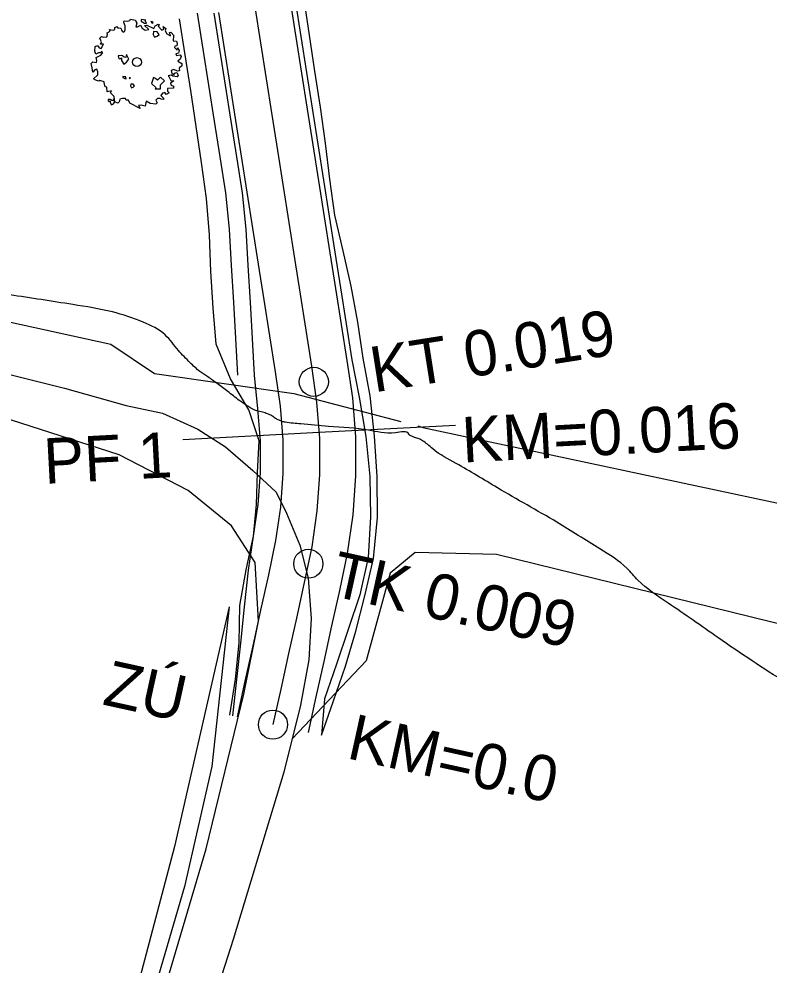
# Model space of a CAD drawing. Extents: x -477701 to -476785, y -1116511 to -1115314.
# Drawn here: x -477305.1 to -477263.9, y -1116246.2 to -1116194.2 of the extents above; entities that cross this region are included whole.
import ezdxf

# ---------------------------------------------------------------- set-up
doc = ezdxf.new("R2010")
doc.units = 0
for name, color, linetype in [('1', 7, 'Continuous'), ('BYBLOCK', 7, 'Continuous'), ('hrana_P', 7, 'Continuous'), ('hrana_R', 7, 'Continuous'), ('IP_RBK', 7, 'Continuous'), ('POLYGONY_SITUACE_PF', 7, 'Continuous'), ('POLYGONY_SITUACE_PF_POPISY', 7, 'Continuous'), ('POLYGONY_SITUACE_PO', 7, 'Continuous'), ('SVK_STAT', 7, 'Continuous'), ('Vrstevnice_vedlejsi', 7, 'Continuous')]:
    doc.layers.add(name, color=color, linetype=linetype)

msp = doc.modelspace()

# ---------------------------------------------------------------- linework, layer by layer
at = {"layer": 'hrana_P'}
for points in [[(-477289.157, -1116195.055), (-477289.457, -1116193.078)], [(-477295.992, -1116196.133), (-477296.298, -1116194.157)], [(-477288.856, -1116197.033), (-477289.157, -1116195.055)], [(-477295.686, -1116198.109), (-477295.992, -1116196.133)], [(-477288.556, -1116199.01), (-477288.856, -1116197.033)], [(-477295.381, -1116200.086), (-477295.686, -1116198.109)], [(-477288.281, -1116200.991), (-477288.556, -1116199.01)], [(-477295.098, -1116202.066), (-477295.381, -1116200.086)], [(-477288.031, -1116202.977), (-477288.281, -1116200.991)], [(-477294.816, -1116204.046), (-477295.098, -1116202.066)], [(-477287.755, -1116204.958), (-477288.031, -1116202.977)], [(-477294.65, -1116206.045), (-477294.816, -1116204.046)], [(-477287.314, -1116206.913), (-477287.755, -1116204.958)], [(-477294.576, -1116208.058), (-477294.65, -1116206.045)], [(-477286.873, -1116208.868), (-477287.314, -1116206.913)], [(-477294.444, -1116210.062), (-477294.576, -1116208.058)], [(-477286.508, -1116210.835), (-477286.873, -1116208.868)], [(-477294.284, -1116212.061), (-477294.444, -1116210.062)], [(-477286.213, -1116212.814), (-477286.508, -1116210.835)], [(-477293.502, -1116213.963), (-477294.284, -1116212.061)], [(-477285.823, -1116214.902), (-477286.213, -1116212.814)], [(-477292.484, -1116215.668), (-477293.502, -1116213.963)], [(-477285.587, -1116217.111), (-477285.823, -1116214.902)], [(-477291.919, -1116217.368), (-477292.484, -1116215.668)], [(-477292.011, -1116219.119), (-477291.919, -1116217.368)], [(-477285.428, -1116219.34), (-477285.587, -1116217.111)], [(-477292.073, -1116220.868), (-477292.011, -1116219.119)], [(-477285.425, -1116221.587), (-477285.428, -1116219.34)], [(-477292.236, -1116222.618), (-477292.073, -1116220.868)], [(-477285.632, -1116223.832), (-477285.425, -1116221.587)], [(-477292.629, -1116224.463), (-477292.236, -1116222.618)], [(-477286.111, -1116225.897), (-477285.632, -1116223.832)], [(-477292.984, -1116226.433), (-477292.629, -1116224.463)], [(-477286.601, -1116227.837), (-477286.111, -1116225.897)], [(-477293.014, -1116228.474), (-477292.984, -1116226.433)], [(-477287.183, -1116229.757), (-477286.601, -1116227.837)], [(-477293.222, -1116230.476), (-477293.014, -1116228.474)], [(-477287.84, -1116231.66), (-477287.183, -1116229.757)], [(-477293.532, -1116232.455), (-477293.222, -1116230.476)], [(-477288.503, -1116233.562), (-477287.84, -1116231.66)]]:
    msp.add_lwpolyline(points, dxfattribs=at)
at = {"layer": 'hrana_R'}
for points in [[(-477289.881, -1116195.169), (-477290.192, -1116193.194)], [(-477289.945, -1116193.155), (-477289.634, -1116195.131)], [(-477294.998, -1116195.831), (-477295.309, -1116193.856)], [(-477294.079, -1116195.831), (-477294.39, -1116193.856)], [(-477293.832, -1116195.792), (-477294.143, -1116193.817)], [(-477292.168, -1116193.505), (-477291.856, -1116195.481)], [(-477291.856, -1116195.481), (-477291.545, -1116197.457)], [(-477289.569, -1116197.145), (-477289.881, -1116195.169)], [(-477289.634, -1116195.131), (-477289.322, -1116197.106)], [(-477294.686, -1116197.807), (-477294.998, -1116195.831)], [(-477293.767, -1116197.807), (-477294.079, -1116195.831)], [(-477293.52, -1116197.768), (-477293.832, -1116195.792)], [(-477289.322, -1116197.106), (-477289.011, -1116199.082)], [(-477291.545, -1116197.457), (-477291.233, -1116199.432)], [(-477289.258, -1116199.121), (-477289.569, -1116197.145)], [(-477294.375, -1116199.783), (-477294.686, -1116197.807)], [(-477293.456, -1116199.783), (-477293.767, -1116197.807)], [(-477293.209, -1116199.744), (-477293.52, -1116197.768)], [(-477288.946, -1116201.096), (-477289.258, -1116199.121)], [(-477289.011, -1116199.082), (-477288.699, -1116201.057)], [(-477292.897, -1116201.719), (-477293.209, -1116199.744)], [(-477291.233, -1116199.432), (-477290.922, -1116201.408)], [(-477294.063, -1116201.758), (-477294.375, -1116199.783)], [(-477293.144, -1116201.758), (-477293.456, -1116199.783)], [(-477288.635, -1116203.072), (-477288.946, -1116201.096)], [(-477288.699, -1116201.057), (-477288.388, -1116203.033)], [(-477293.752, -1116203.734), (-477294.063, -1116201.758)], [(-477292.833, -1116203.734), (-477293.144, -1116201.758)], [(-477292.586, -1116203.695), (-477292.897, -1116201.719)], [(-477290.922, -1116201.408), (-477290.61, -1116203.383)], [(-477290.61, -1116203.383), (-477290.299, -1116205.359)], [(-477288.323, -1116205.047), (-477288.635, -1116203.072)], [(-477288.388, -1116203.033), (-477288.076, -1116205.009)], [(-477293.552, -1116205.727), (-477293.752, -1116203.734)], [(-477292.633, -1116205.727), (-477292.833, -1116203.734)], [(-477292.275, -1116205.67), (-477292.586, -1116203.695)], [(-477290.299, -1116205.359), (-477289.987, -1116207.335)], [(-477288.012, -1116207.023), (-477288.323, -1116205.047)], [(-477288.076, -1116205.009), (-477287.765, -1116206.984)], [(-477293.438, -1116207.734), (-477293.552, -1116205.727)], [(-477292.519, -1116207.734), (-477292.633, -1116205.727)], [(-477291.963, -1116207.646), (-477292.275, -1116205.67)], [(-477287.7, -1116208.999), (-477288.012, -1116207.023)], [(-477287.765, -1116206.984), (-477287.453, -1116208.96)], [(-477289.987, -1116207.335), (-477289.676, -1116209.31)], [(-477293.324, -1116209.74), (-477293.438, -1116207.734)], [(-477292.405, -1116209.74), (-477292.519, -1116207.734)], [(-477291.652, -1116209.622), (-477291.963, -1116207.646)], [(-477287.389, -1116210.974), (-477287.7, -1116208.999)], [(-477287.453, -1116208.96), (-477287.142, -1116210.935)], [(-477291.34, -1116211.597), (-477291.652, -1116209.622)], [(-477289.676, -1116209.31), (-477289.365, -1116211.286)], [(-477293.21, -1116211.747), (-477293.324, -1116209.74)], [(-477292.291, -1116211.747), (-477292.405, -1116209.74)], [(-477287.078, -1116212.95), (-477287.389, -1116210.974)], [(-477287.142, -1116210.935), (-477286.831, -1116212.911)], [(-477291.029, -1116213.573), (-477291.34, -1116211.597)], [(-477289.365, -1116211.286), (-477289.053, -1116213.261)], [(-477293.096, -1116213.754), (-477293.21, -1116211.747)], [(-477292.177, -1116213.754), (-477292.291, -1116211.747)], [(-477289.053, -1116213.261), (-477288.765, -1116215.24)], [(-477286.778, -1116215.012), (-477287.078, -1116212.95)], [(-477286.831, -1116212.911), (-477286.418, -1116214.97)], [(-477293.096, -1116213.754), (-477293.096, -1116213.754)], [(-477291.994, -1116215.612), (-477292.177, -1116213.754)], [(-477290.752, -1116215.469), (-477291.029, -1116213.573)], [(-477288.765, -1116215.24), (-477288.61, -1116217.234)], [(-477286.612, -1116217.153), (-477286.778, -1116215.012)], [(-477286.418, -1116214.97), (-477286.052, -1116217.13)], [(-477291.858, -1116217.365), (-477291.994, -1116215.612)], [(-477290.609, -1116217.315), (-477290.752, -1116215.469)], [(-477291.852, -1116219.124), (-477291.858, -1116217.365)], [(-477290.602, -1116219.166), (-477290.609, -1116217.315)], [(-477288.61, -1116217.234), (-477288.603, -1116219.233)], [(-477286.604, -1116219.301), (-477286.612, -1116217.153)], [(-477286.052, -1116217.13), (-477285.846, -1116219.326)], [(-477291.976, -1116220.879), (-477291.852, -1116219.124)], [(-477290.733, -1116221.013), (-477290.602, -1116219.166)], [(-477288.603, -1116219.233), (-477288.744, -1116221.228)], [(-477286.756, -1116221.443), (-477286.604, -1116219.301)], [(-477285.846, -1116219.326), (-477285.804, -1116221.546)], [(-477292.229, -1116222.619), (-477291.976, -1116220.879)], [(-477291, -1116222.845), (-477290.733, -1116221.013)], [(-477288.744, -1116221.228), (-477289.033, -1116223.207)], [(-477287.066, -1116223.568), (-477286.756, -1116221.443)], [(-477285.804, -1116221.546), (-477285.928, -1116223.777)], [(-477292.507, -1116224.49), (-477292.229, -1116222.619)], [(-477291.4, -1116224.733), (-477291, -1116222.845)], [(-477289.033, -1116223.207), (-477289.447, -1116225.163)], [(-477287.493, -1116225.593), (-477287.066, -1116223.568)], [(-477285.928, -1116223.777), (-477286.387, -1116225.837)], [(-477292.721, -1116226.49), (-477292.507, -1116224.49)], [(-477291.83, -1116226.687), (-477291.4, -1116224.733)], [(-477289.447, -1116225.163), (-477289.877, -1116227.116)], [(-477287.923, -1116227.546), (-477287.493, -1116225.593)], [(-477286.387, -1116225.837), (-477287.032, -1116227.742)], [(-477292.935, -1116228.491), (-477292.721, -1116226.49)], [(-477292.26, -1116228.64), (-477291.83, -1116226.687)], [(-477289.877, -1116227.116), (-477290.306, -1116229.07)], [(-477288.353, -1116229.5), (-477287.923, -1116227.546)], [(-477287.032, -1116227.742), (-477287.678, -1116229.648)], [(-477293.149, -1116230.492), (-477292.935, -1116228.491)], [(-477292.689, -1116230.593), (-477292.26, -1116228.64)], [(-477290.306, -1116229.07), (-477290.736, -1116231.023)], [(-477288.783, -1116231.453), (-477288.353, -1116229.5)], [(-477287.678, -1116229.648), (-477288.323, -1116231.554)], [(-477293.363, -1116232.493), (-477293.149, -1116230.492)], [(-477293.119, -1116232.546), (-477292.689, -1116230.593)], [(-477290.736, -1116231.023), (-477291.166, -1116232.976)], [(-477289.213, -1116233.406), (-477288.783, -1116231.453)], [(-477288.323, -1116231.554), (-477288.503, -1116233.562)]]:
    msp.add_lwpolyline(points, dxfattribs=at)
at = {"layer": 'IP_RBK'}
for points in [[(-477297.207, -1116194.574), (-477297.058, -1116194.688), (-477297.092, -1116194.817), (-477297.001, -1116194.993), (-477296.792, -1116195.088), (-477296.858, -1116194.917), (-477296.78, -1116194.894), (-477296.6, -1116195.087), (-477296.635, -1116195.076), (-477296.649, -1116195.371), (-477296.468, -1116195.392), (-477296.428, -1116195.521), (-477296.451, -1116195.639), (-477296.555, -1116195.664), (-477296.584, -1116195.735), (-477296.433, -1116195.888), (-477296.412, -1116195.764), (-477296.319, -1116195.906), (-477296.356, -1116196.04), (-477296.509, -1116196.091), (-477296.462, -1116196.185), (-477296.269, -1116196.143), (-477296.214, -1116196.236), (-477296.273, -1116196.372), (-477296.391, -1116196.486), (-477296.178, -1116196.614), (-477296.182, -1116196.737), (-477296.325, -1116196.866), (-477296.31, -1116197.021), (-477296.418, -1116197.045), (-477296.608, -1116196.954), (-477296.753, -1116197.002), (-477296.728, -1116197.161), (-477296.592, -1116197.245), (-477296.603, -1116197.161), (-477296.535, -1116197.124), (-477296.445, -1116197.106), (-477296.372, -1116197.259), (-477296.437, -1116197.348), (-477296.663, -1116197.318), (-477296.74, -1116197.267), (-477296.932, -1116197.294), (-477296.911, -1116197.302), (-477296.771, -1116197.551), (-477296.608, -1116197.572), (-477296.796, -1116197.695), (-477296.758, -1116197.816), (-477296.625, -1116197.872), (-477296.628, -1116197.969), (-477296.954, -1116197.986), (-477296.961, -1116198.146), (-477296.87, -1116198.223), (-477297.033, -1116198.316), (-477297.101, -1116198.216), (-477297.238, -1116198.247), (-477297.32, -1116198.371), (-477297.178, -1116198.519), (-477297.176, -1116198.606), (-477297.311, -1116198.586), (-477297.381, -1116198.54), (-477297.503, -1116198.545), (-477297.61, -1116198.628), (-477297.533, -1116198.787), (-477297.598, -1116198.847), (-477297.909, -1116198.814), (-477298.138, -1116198.692), (-477298.197, -1116198.963), (-477298.405, -1116198.908), (-477298.552, -1116198.924), (-477298.459, -1116199.093), (-477299.036, -1116198.793), (-477299.105, -1116198.631), (-477299.234, -1116198.625), (-477299.262, -1116198.55), (-477299.443, -1116198.547), (-477299.58, -1116198.574), (-477299.609, -1116198.73), (-477299.696, -1116198.8), (-477299.852, -1116198.72), (-477299.884, -1116198.437), (-477300.092, -1116198.235), (-477300.032, -1116198.123), (-477300.276, -1116198.168), (-477300.292, -1116197.923), (-477300.381, -1116197.896), (-477300.444, -1116197.671), (-477300.444, -1116197.618), (-477300.674, -1116197.556), (-477300.741, -1116197.594), (-477300.899, -1116197.535), (-477301.025, -1116197.455), (-477300.789, -1116197.245), (-477300.783, -1116197.078), (-477300.851, -1116196.936), (-477300.959, -1116196.971), (-477301.066, -1116197.098), (-477301.097, -1116196.86), (-477301.157, -1116196.613), (-477301.06, -1116196.526), (-477300.871, -1116196.567), (-477300.852, -1116196.443), (-477300.884, -1116196.292), (-477300.626, -1116196.159), (-477300.528, -1116196.045), (-477300.546, -1116195.951), (-477300.643, -1116196.028), (-477300.758, -1116196.028), (-477300.893, -1116196.112), (-477300.947, -1116195.938), (-477300.932, -1116195.685), (-477300.812, -1116195.636), (-477300.709, -1116195.757), (-477300.6, -1116195.797), (-477300.498, -1116195.586), (-477300.488, -1116195.551), (-477300.642, -1116195.549), (-477300.584, -1116195.431), (-477300.629, -1116195.358), (-477300.672, -1116195.228), (-477300.582, -1116195.125), (-477300.479, -1116195.17), (-477300.3, -1116195.152), (-477300.255, -1116195.014), (-477300.274, -1116194.928), (-477300.115, -1116194.84), (-477300.156, -1116194.747), (-477299.951, -1116194.79), (-477299.86, -1116194.738), (-477299.864, -1116194.634), (-477299.729, -1116194.589), (-477299.716, -1116194.659), (-477299.634, -1116194.652), (-477299.546, -1116194.678), (-477299.512, -1116194.717), (-477299.497, -1116194.783), (-477299.455, -1116194.843), (-477299.401, -1116194.885), (-477299.317, -1116194.861), (-477299.281, -1116194.761), (-477299.28, -1116194.541), (-477299.354, -1116194.37), (-477299.345, -1116194.266), (-477299.163, -1116194.297), (-477299.033, -1116194.252), (-477299.001, -1116194.174), (-477298.729, -1116194.235), (-477298.707, -1116194.303), (-477298.645, -1116194.398), (-477298.7, -1116194.596), (-477298.601, -1116194.603), (-477298.445, -1116194.516), (-477298.348, -1116194.674), (-477298.182, -1116194.784), (-477297.979, -1116194.741), (-477298.234, -1116194.518), (-477298.098, -1116194.506), (-477297.721, -1116194.683), (-477297.639, -1116194.548), (-477297.471, -1116194.448), (-477297.425, -1116194.468), (-477297.473, -1116194.571), (-477297.265, -1116194.775), (-477297.169, -1116194.732)], [(-477298.405, -1116194.283), (-477298.228, -1116194.395), (-477298.112, -1116194.41), (-477298.186, -1116194.256), (-477298.155, -1116194.232), (-477298.402, -1116194.196)], [(-477297.88, -1116194.316), (-477297.804, -1116194.395), (-477297.756, -1116194.357), (-477297.78, -1116194.322)], [(-477297.723, -1116194.863), (-477297.75, -1116195.019), (-477297.673, -1116195.169), (-477297.534, -1116195.118), (-477297.425, -1116195.014), (-477297.538, -1116194.877)], [(-477299.498, -1116196.303), (-477299.498, -1116196.445), (-477299.37, -1116196.647), (-477299.218, -1116196.551), (-477299.091, -1116196.376), (-477299.213, -1116196.116), (-477299.244, -1116196.292), (-477299.346, -1116196.274), (-477299.442, -1116196.204), (-477299.484, -1116196.173), (-477299.672, -1116196.196), (-477299.66, -1116196.29), (-477299.61, -1116196.366), (-477299.537, -1116196.336)], [(-477299.412, -1116197.378), (-477299.298, -1116197.45), (-477299.224, -1116197.46), (-477299.272, -1116197.361), (-477299.251, -1116197.345), (-477299.41, -1116197.323)], [(-477299.075, -1116197.399), (-477299.026, -1116197.45), (-477298.995, -1116197.426), (-477299.011, -1116197.404)], [(-477297.73, -1116197.387), (-477297.844, -1116197.714), (-477297.583, -1116197.955), (-477297.632, -1116198.009), (-477297.342, -1116198.016), (-477297.337, -1116197.796), (-477297.129, -1116197.574), (-477297.35, -1116197.365), (-477297.509, -1116197.534), (-477297.613, -1116197.437)], [(-477298.975, -1116197.75), (-477298.992, -1116197.85), (-477298.942, -1116197.947), (-477298.853, -1116197.914), (-477298.783, -1116197.847), (-477298.856, -1116197.759)], [(-477300.113, -1116198.674), (-477300.113, -1116198.765), (-477300.031, -1116198.895), (-477299.933, -1116198.833), (-477299.852, -1116198.72), (-477299.93, -1116198.554), (-477299.95, -1116198.667), (-477300.015, -1116198.655), (-477300.077, -1116198.61), (-477300.104, -1116198.591), (-477300.224, -1116198.605), (-477300.217, -1116198.666), (-477300.184, -1116198.714), (-477300.138, -1116198.695)]]:
    msp.add_lwpolyline(points, close=True, dxfattribs=at)
msp.add_circle((-477298.636, -1116196.543), 0.247, dxfattribs=at)
at = {"layer": 'POLYGONY_SITUACE_PF'}
msp.add_lwpolyline([(-477296.115, -1116217.295), (-477288.626, -1116216.898), (-477281.136, -1116216.501)], dxfattribs=at)
at = {"layer": 'POLYGONY_SITUACE_PO'}
for centre in [(-477288.918, -1116214.122), (-477289.219, -1116224.129), (-477291.166, -1116232.976)]:
    msp.add_circle(centre, 0.8, dxfattribs=at)
at = {"layer": 'SVK_STAT'}
for p, q in [((-477283.355, -1116223.508), (-477284.728, -1116224.652)), ((-477278.884, -1116223.619), (-477283.355, -1116223.508)), ((-477250.888, -1116230.512), (-477278.884, -1116223.619)), ((-477284.728, -1116224.652), (-477286.037, -1116229.473)), ((-477286.037, -1116229.473), (-477290.109, -1116233.753))]:
    msp.add_line(p, q, dxfattribs=at)
for points in [[(-477378.434, -1116194.951), (-477368.559, -1116197.136), (-477357.876, -1116199.954), (-477345.308, -1116202.968), (-477334.412, -1116205.619), (-477325.495, -1116208.334), (-477318.164, -1116210.281), (-477310.509, -1116212.508), (-477302.618, -1116214.478), (-477299.225, -1116215.422), (-477297.234, -1116215.854), (-477295.285, -1116216.725), (-477293.777, -1116217.695), (-477292.279, -1116219.01), (-477290.987, -1116220.188), (-477290.426, -1116221.344), (-477289.69, -1116223.1), (-477289.227, -1116224.927), (-477289.06, -1116227.135), (-477289.185, -1116229.412), (-477289.652, -1116231.908), (-477290.566, -1116235.599), (-477293.357, -1116244.798), (-477297.071, -1116256.408)], [(-477299.069, -1116254.134), (-477294.829, -1116239.803), (-477292.758, -1116231.298), (-477291.962, -1116227.294), (-477292.15, -1116224.052), (-477293.437, -1116222.049), (-477295.827, -1116220.095), (-477299.621, -1116218.141), (-477307.205, -1116215.695), (-477319.431, -1116212.241), (-477328.866, -1116209.607), (-477335.811, -1116207.673), (-477346.174, -1116205.125), (-477353.658, -1116203.391), (-477366.762, -1116200.095), (-477377.776, -1116197.772)], [(-477363.217, -1116198.545), (-477333.842, -1116204.652), (-477300.075, -1116212.044), (-477297.67, -1116213.661), (-477290.025, -1116214.775), (-477284.144, -1116216.308)], [(-477283.206, -1116216.553), (-477282.917, -1116216.628), (-477247.656, -1116224.149), (-477219.752, -1116229.156), (-477203.382, -1116232.679)], [(-477293.576, -1116226.506), (-477296.573, -1116239.688), (-477300.903, -1116256.076), (-477304.435, -1116267.91)], [(-477293.576, -1116226.506), (-477294.529, -1116235.276), (-477296.029, -1116241.883), (-477298.797, -1116251.356), (-477301.491, -1116260.971), (-477303.533, -1116267.596)]]:
    msp.add_lwpolyline(points, dxfattribs=at)
at = {"layer": 'Vrstevnice_vedlejsi'}
for points in [[(-477199.82, -1116204.007), (-477200.739, -1116202.514), (-477201.27, -1116201.82), (-477201.875, -1116201.179), (-477202.552, -1116200.589), (-477207.089, -1116196.656), (-477215.486, -1116189.38), (-477227.743, -1116178.759), (-477238.175, -1116170.775), (-477246.781, -1116165.426), (-477253.562, -1116162.713), (-477260.267, -1116160.417), (-477266.895, -1116158.537), (-477273.448, -1116157.075), (-477281.2, -1116155.527), (-477290.151, -1116153.893), (-477300.303, -1116152.173), (-477308.131, -1116150.906), (-477313.636, -1116150.091), (-477316.818, -1116149.728), (-477320.571, -1116149.036), (-477324.896, -1116148.014), (-477329.793, -1116146.662), (-477335.87, -1116145.7), (-477343.126, -1116145.128), (-477351.563, -1116144.945), (-477360.546, -1116145.429), (-477370.073, -1116146.581), (-477380.147, -1116148.401), (-477387.949, -1116149.722), (-477393.48, -1116150.545), (-477396.74, -1116150.87), (-477399.688, -1116151.291), (-477402.323, -1116151.808), (-477404.646, -1116152.421), (-477408.076, -1116153.604), (-477412.612, -1116155.356), (-477418.255, -1116157.678), (-477423.245, -1116160.053), (-477427.583, -1116162.482), (-477431.268, -1116164.964), (-477433.964, -1116166.824), (-477435.672, -1116168.061), (-477436.392, -1116168.675), (-477437.552, -1116170.019), (-477439.151, -1116172.092), (-477441.189, -1116174.894), (-477442.91, -1116177.326), (-477444.315, -1116179.388), (-477445.403, -1116181.079), (-477446.061, -1116182.396), (-477446.29, -1116183.339), (-477446.09, -1116183.907), (-477445.933, -1116184.419), (-477445.817, -1116184.875), (-477445.745, -1116185.274), (-477445.711, -1116185.587), (-477445.716, -1116185.814), (-477445.759, -1116185.955), (-477446.027, -1116186.053), (-477446.522, -1116186.11), (-477447.242, -1116186.125), (-477448.164, -1116186.21), (-477449.287, -1116186.365), (-477450.611, -1116186.591), (-477451.625, -1116186.841), (-477452.328, -1116187.116), (-477452.721, -1116187.414), (-477453.447, -1116187.653), (-477454.505, -1116187.832), (-477455.895, -1116187.952), (-477457.34, -1116187.983), (-477458.839, -1116187.924), (-477460.392, -1116187.776), (-477461.247, -1116187.707)], [(-477453.209, -1116210.761), (-477447.63, -1116207.098), (-477441.8, -1116203.305), (-477437.77, -1116200.726), (-477435.54, -1116199.361), (-477434.308, -1116198.427), (-477434.076, -1116197.924), (-477434.186, -1116197.871), (-477434.417, -1116197.911), (-477434.843, -1116197.852), (-477435.029, -1116197.283), (-477434.636, -1116196.216), (-477433.662, -1116194.651), (-477432.521, -1116193.659), (-477431.212, -1116193.239), (-477429.735, -1116193.391), (-477428.556, -1116193.508), (-477427.673, -1116193.591), (-477427.087, -1116193.639), (-477425.968, -1116193.654), (-477424.314, -1116193.634), (-477422.127, -1116193.581), (-477419.527, -1116193.525), (-477416.512, -1116193.466), (-477413.083, -1116193.404), (-477410.774, -1116193.339), (-477409.583, -1116193.271), (-477409.511, -1116193.2), (-477409.092, -1116193.047), (-477408.325, -1116192.812), (-477407.212, -1116192.496), (-477406.453, -1116192.207), (-477406.047, -1116191.946), (-477405.996, -1116191.711), (-477405.956, -1116191.405), (-477405.927, -1116191.029), (-477405.91, -1116190.583), (-477405.886, -1116190.269), (-477405.856, -1116190.088), (-477405.819, -1116190.039), (-477404.813, -1116189.277), (-477402.837, -1116187.801), (-477399.893, -1116185.612), (-477397.343, -1116184.037), (-477395.187, -1116183.076), (-477393.427, -1116182.73), (-477390.441, -1116182.062), (-477386.229, -1116181.071), (-477380.792, -1116179.759), (-477376.39, -1116178.596), (-477373.023, -1116177.582), (-477370.692, -1116176.717), (-477368.571, -1116175.951), (-477366.661, -1116175.284), (-477364.961, -1116174.716), (-477363.59, -1116174.267), (-477362.55, -1116173.939), (-477361.839, -1116173.732), (-477360.359, -1116173.594), (-477358.11, -1116173.527), (-477355.092, -1116173.529), (-477350.007, -1116173.611), (-477342.855, -1116173.772), (-477333.637, -1116174.013), (-477327.001, -1116174.258), (-477322.946, -1116174.507), (-477321.473, -1116174.76), (-477318.314, -1116175.527), (-477313.468, -1116176.809), (-477306.935, -1116178.606), (-477300.313, -1116180.316), (-477293.602, -1116181.939), (-477286.801, -1116183.474), (-477278.779, -1116186.164), (-477269.536, -1116190.007), (-477259.071, -1116195.003), (-477251.273, -1116198.758), (-477246.141, -1116201.269)], [(-477239.205, -1116245.168), (-477239.572, -1116244.424), (-477241.085, -1116241.909), (-477242.17, -1116240.955), (-477244.658, -1116239.563), (-477248.548, -1116237.733), (-477253.84, -1116235.466), (-477258.631, -1116233.12), (-477262.92, -1116230.694), (-477266.708, -1116228.189), (-477269.434, -1116226.302), (-477271.099, -1116225.033), (-477271.702, -1116224.382), (-477273.191, -1116223.318), (-477275.566, -1116221.843), (-477278.827, -1116219.954), (-477281.097, -1116218.611), (-477282.378, -1116217.813), (-477282.669, -1116217.56), (-477282.94, -1116217.367), (-477283.19, -1116217.234), (-477283.42, -1116217.161), (-477283.579, -1116217.1), (-477283.667, -1116217.05), (-477283.686, -1116217.013), (-477284.432, -1116216.922), (-477285.906, -1116216.78), (-477288.109, -1116216.584), (-477289.634, -1116216.44), (-477290.481, -1116216.349), (-477290.651, -1116216.309), (-477290.831, -1116216.237), (-477291.022, -1116216.134), (-477291.223, -1116215.999), (-477291.463, -1116215.885), (-477291.742, -1116215.792), (-477292.059, -1116215.719), (-477292.483, -1116215.505), (-477293.014, -1116215.149), (-477293.652, -1116214.651), (-477294.226, -1116214.219), (-477294.736, -1116213.853), (-477295.183, -1116213.552), (-477295.725, -1116213.067), (-477296.36, -1116212.398), (-477297.09, -1116211.545), (-477298.301, -1116210.84), (-477299.993, -1116210.283), (-477302.167, -1116209.874), (-477305.631, -1116209.344), (-477310.385, -1116208.691), (-477316.43, -1116207.916), (-477321.488, -1116207.207), (-477325.559, -1116206.564), (-477328.643, -1116205.988), (-477330.734, -1116205.608), (-477331.831, -1116205.423), (-477331.936, -1116205.435), (-477332.254, -1116205.438), (-477332.788, -1116205.431), (-477333.535, -1116205.415), (-477334.323, -1116205.362), (-477335.151, -1116205.272), (-477336.02, -1116205.144), (-477336.719, -1116205.235), (-477337.249, -1116205.546), (-477337.609, -1116206.075), (-477338.752, -1116206.241), (-477340.677, -1116206.044), (-477343.385, -1116205.484), (-477345.233, -1116205.125), (-477346.219, -1116204.968), (-477346.345, -1116205.012), (-477347.304, -1116205.293), (-477349.094, -1116205.811), (-477351.717, -1116206.566), (-477354.676, -1116207.267), (-477357.972, -1116207.912), (-477361.605, -1116208.502), (-477364.648, -1116209.47), (-477367.103, -1116210.815), (-477367.59, -1116211.224), (-477368.033, -1116211.684), (-477368.477, -1116212.14), (-477368.969, -1116212.538), (-477372.342, -1116214.432), (-477377.221, -1116216.497), (-477383.606, -1116218.734), (-477388.352, -1116220.049), (-477391.46, -1116220.442), (-477391.833, -1116220.367), (-477392.195, -1116220.201), (-477392.557, -1116220.023), (-477392.929, -1116219.913), (-477394.534, -1116219.919), (-477396.275, -1116220.461), (-477398.151, -1116221.538), (-477400.026, -1116222.67), (-477401.901, -1116223.858)]]:
    msp.add_spline(points, degree=3, dxfattribs=at)

# ---------------------------------------------------------------- texts
at = {"layer": '1'}
for s, rotation, p in [('KT 0.019', 8.9589, (-477285.606, -1116214.71)), ('TK 0.009', 347.5887, (-477288.083, -1116225.865))]:
    msp.add_text(s, height=2.5, rotation=rotation, dxfattribs=at).set_placement(p)
at = {"layer": 'BYBLOCK'}
msp.add_text('ZÚ          KM=0.0', height=2.5, rotation=347.5887, dxfattribs=at).set_placement((-477300.6, -1116231.858))
at = {"layer": 'POLYGONY_SITUACE_PF_POPISY'}
for s, p in [('KM=0.016', (-477280.72, -1116218.567)), ('PF 1', (-477303.707, -1116219.738))]:
    msp.add_text(s, height=2.5, rotation=3.0324, dxfattribs=at).set_placement(p)

doc.saveas('drawing.dxf')
